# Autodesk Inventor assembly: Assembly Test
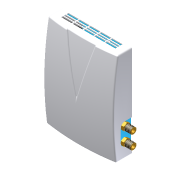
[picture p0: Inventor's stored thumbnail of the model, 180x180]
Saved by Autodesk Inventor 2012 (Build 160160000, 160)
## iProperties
Created: 2011-01
Part Number: Assembly Test
Document SubType Name: Assembly
Designer: Beta-8540w
Author: Beta-8540w
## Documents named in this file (6)
- C:\Users\VMuser\Desktop\Inventor 2012 Essentials\Assemblies\Chapter 14\c14-01.iam
- C:\Users\VMuser\Desktop\Inventor 2012 Essentials\Content Center Files\en-US\Parker Hex Nipple 216P\Parker Hex Nipple 216P 216P-4.ipt
- C:\Users\VMuser\Desktop\Inventor 2012 Essentials\Parts\Chapter 14\c14-03.ipt
- C:\Users\VMuser\Desktop\Inventor 2012 Essentials\Parts\Chapter 14\c14-04.ipt
- C:\Users\VMuser\Desktop\Inventor 2012 Essentials\Parts\Chapter 14\c14-05.ipt
- C:\Users\VMuser\Desktop\Inventor 2012 Essentials\Parts\Chapter 14\c14-06.ipt
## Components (6 placed, 5 different names)
1. c14-03:1 — Insert:1, Insert:2, Flush:1, Flush:2, Flush:3, Mate:1, Mate:2, Mate:3
2. Parker Hex Nipple 216P 216P-4:3 — Insert:1
3. Parker Hex Nipple 216P 216P-4:4 — Insert:2
4. c14-04:1 — Flush:3, Mate:1, Mate:2, Mate:3
5. c14-05:1 — Flush:1
6. c14-06:1 — Flush:2
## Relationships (8: Flush 3, Mate 3, Insert 2)
- Insert:1: c14-03:1 ↔ Parker Hex Nipple 216P 216P-4:3
- Insert:2: c14-03:1 ↔ Parker Hex Nipple 216P 216P-4:4
- Flush:1: c14-03:1 ↔ c14-05:1
- Flush:2: c14-03:1 ↔ c14-06:1
- Flush:3: c14-03:1 ↔ c14-04:1
- Mate:1: c14-03:1 ↔ c14-04:1
- Mate:2: c14-03:1 ↔ c14-04:1
- Mate:3: c14-03:1 ↔ c14-04:1
